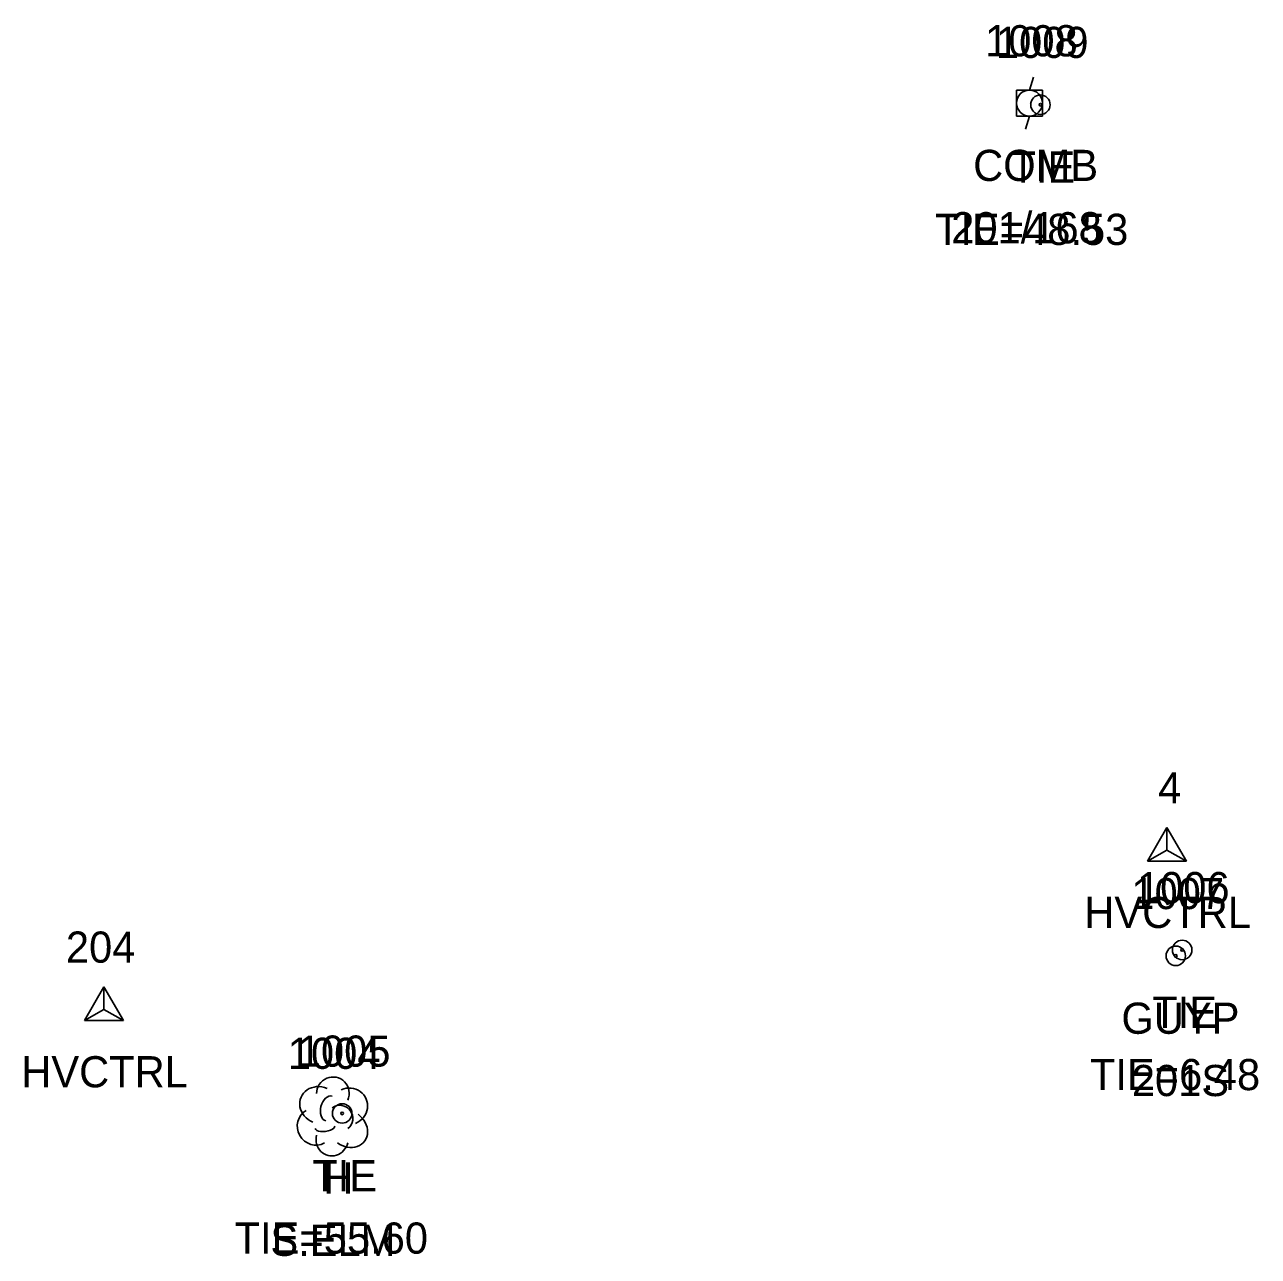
# Model space of a CAD drawing. Extents: x 1505684 to 1510253, y 730355 to 731397.
# Drawn here: x 1509065 to 1509144.2, y 730443.5 to 730522.6 of the extents above; entities that cross this region are included whole.
import ezdxf

# ---------------------------------------------------------------- set-up
doc = ezdxf.new("R2010")
doc.units = 0
for name, color, linetype in [('C_A', 7, 'Continuous'), ('C_C', 7, 'Continuous'), ('C_I', 7, 'Continuous'), ('CBP', 7, 'Continuous'), ('CPSM', 7, 'Continuous'), ('L_A', 7, 'Continuous'), ('L_C', 7, 'Continuous'), ('L_I', 7, 'Continuous'), ('LTD', 7, 'Continuous'), ('U_A', 7, 'Continuous'), ('U_C', 7, 'Continuous'), ('U_I', 7, 'Continuous'), ('UP', 7, 'Continuous'), ('UPGW', 7, 'Continuous')]:
    doc.layers.add(name, color=color, linetype=linetype)

msp = doc.modelspace()

# ---------------------------------------------------------------- linework, layer by layer
at = {"layer": 'CBP'}
for centre, radius in [((1509130.21, 730517.431), 0.625), ((1509130.21, 730517.431), 0.0833), ((1509139.314, 730463.184), 0.625), ((1509139.314, 730463.184), 0.0833), ((1509085.372, 730452.692), 0.625), ((1509085.372, 730452.692), 0.0833)]:
    msp.add_circle(centre, radius, dxfattribs=at)
at = {"layer": 'CPSM'}
for p, q in [((1509137.088, 730468.872), (1509138.338, 730471.037)), ((1509139.588, 730468.872), (1509138.338, 730471.037)), ((1509138.339, 730469.593), (1509138.338, 730471.037)), ((1509137.088, 730468.872), (1509138.339, 730469.593)), ((1509138.339, 730469.593), (1509138.339, 730469.593)), ((1509138.339, 730469.593), (1509139.588, 730468.872)), ((1509137.088, 730468.872), (1509139.588, 730468.872)), ((1509068.819, 730458.645), (1509070.069, 730460.81)), ((1509071.319, 730458.645), (1509070.069, 730460.81)), ((1509070.069, 730459.366), (1509070.069, 730460.81)), ((1509068.819, 730458.645), (1509070.069, 730459.366)), ((1509070.069, 730459.366), (1509070.069, 730459.366)), ((1509070.069, 730459.366), (1509071.319, 730458.645)), ((1509068.819, 730458.645), (1509071.319, 730458.645))]:
    msp.add_line(p, q, dxfattribs=at)
at = {"layer": 'LTD'}
msp.add_line((1509084.729, 730452.549), (1509084.729, 730452.549), dxfattribs=at)
msp.add_line((1509084.729, 730452.549), (1509084.729, 730452.549), dxfattribs=at)
msp.add_arc((1509084.776, 730453.983), 1.047, 335.52715, 180.95627, dxfattribs=at)
for centre, major_axis, ratio, start_param, end_param in [((1509083.938, 730453.215), (1.21, -0.512), 0.895232, 1.570796, 4.712389), ((1509084.521, 730453.007), (-0.208, -0.792), 0.645439, 3.141593, 6.283185), ((1509085.771, 730453.132), (-1.141, -0.483), 0.949671, 1.570796, 4.712389), ((1509085.229, 730452.382), (-0.5, 0.667), 0.989748, 3.141593, 6.283185), ((1509083.646, 730451.84), (0.584, -1.042), 0.959034, 3.141593, 6.283185), ((1509085.729, 730451.716), (-1.09, 0.792), 0.841452, 1.570796, 4.712389), ((1509084.271, 730451.799), (-0.625, -0.083), 0.423636, 0, 3.141593), ((1509084.73, 730451.049), (0.265, 1.061), 0.942809, 1.570796, 4.712389)]:
    msp.add_ellipse(centre, major_axis=major_axis, ratio=ratio, start_param=start_param, end_param=end_param, dxfattribs=at)
at = {"layer": 'UP'}
for p, q in [((1509129.756, 730519.204), (1509129.506, 730518.371)), ((1509128.673, 730516.704), (1509128.673, 730518.371)), ((1509128.673, 730518.371), (1509130.339, 730518.371)), ((1509130.339, 730518.371), (1509130.339, 730516.704)), ((1509129.506, 730517.537), (1509129.506, 730517.537)), ((1509130.339, 730516.704), (1509128.673, 730516.704)), ((1509129.256, 730515.871), (1509129.506, 730516.704))]:
    msp.add_line(p, q, dxfattribs=at)
msp.add_circle((1509129.506, 730517.537), 0.833, dxfattribs=at)
at = {"layer": 'UPGW'}
for radius in [0.625, 0.0833]:
    msp.add_circle((1509138.901, 730462.803), radius, dxfattribs=at)

# ---------------------------------------------------------------- texts
at = {"layer": 'C_A'}
for s, p in [('TIE', (1509128.289, 730512.431)), ('HVCTRL', (1509133.032, 730464.593)), ('TIE', (1509137.393, 730458.184)), ('HVCTRL', (1509064.762, 730454.366)), ('TIE', (1509083.45, 730447.692))]:
    msp.add_text(s, height=2, dxfattribs=at).set_placement(p)
at = {"layer": 'C_C'}
for s, p in [('TIE=48.53', (1509123.439, 730508.431)), ('TIE=6.48', (1509133.393, 730454.184)), ('TIE=55.60', (1509078.466, 730443.692))]:
    msp.add_text(s, height=2, dxfattribs=at).set_placement(p)
at = {"layer": 'C_I'}
for s, p in [('1009', (1509127.352, 730520.431)), ('4', (1509137.772, 730472.593)), ('1006', (1509136.409, 730466.184)), ('204', (1509067.628, 730462.366)), ('1005', (1509082.521, 730455.692))]:
    msp.add_text(s, height=2, dxfattribs=at).set_placement(p)
at = {"layer": 'L_A'}
msp.add_text('H', height=2, dxfattribs=at).set_placement((1509084.162, 730447.549))
at = {"layer": 'L_C'}
msp.add_text('S.ELM', height=2, dxfattribs=at).set_placement((1509080.761, 730443.549))
at = {"layer": 'L_I'}
msp.add_text('1004', height=2, dxfattribs=at).set_placement((1509081.879, 730455.549))
at = {"layer": 'U_A'}
for s, p in [('COMB', (1509125.892, 730512.537)), ('GUYP', (1509135.413, 730457.803))]:
    msp.add_text(s, height=2, dxfattribs=at).set_placement(p)
at = {"layer": 'U_C'}
for s, p in [('201/168', (1509124.482, 730508.537)), ('201S', (1509136.082, 730453.803))]:
    msp.add_text(s, height=2, dxfattribs=at).set_placement(p)
at = {"layer": 'U_I'}
for s, p in [('1008', (1509126.656, 730520.537)), ('1007', (1509136.051, 730465.803))]:
    msp.add_text(s, height=2, dxfattribs=at).set_placement(p)

doc.saveas('drawing.dxf')
